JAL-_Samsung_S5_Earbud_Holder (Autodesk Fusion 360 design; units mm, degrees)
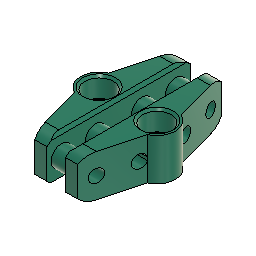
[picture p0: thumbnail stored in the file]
parameter "Structure_Thickness" = 2
parameter "Earbud_Main_Diameter" = 13.6
parameter "Earbud_Inner_Diameter" = 11
parameter "Wrap_Diameter" = 10
parameter "Plug_Diameter" = 6.2
parameter "Primary_Length_Short" = 34
sketch "Primary Layout"
  dimension "d44" = 17.6 (= "Earbud_Main_Diameter + ( Structure_Thickness * 2 )")
  dimension "d45" = 34 (= "Primary_Length_Short")
  dimension "d47" = 7
  dimension "d49" = 2 (= "Structure_Thickness")
  dimension "d50" = 5 (= "7 mm - Structure_Thickness")
extrude "Extrude1" new body sketch "Primary Layout" blind 20 bodies "Main Body"
sketch "Earbud holes" plane through (0, 0, 20) normal (0, 0, 1) x axis (-1, 0, 0)
  dimension "d55" = 13.6 (= "Earbud_Main_Diameter")
  dimension "d56" = 13.6 (= "Earbud_Main_Diameter")
  dimension "d57" = 11 (= "Earbud_Inner_Diameter")
  dimension "d58" = 11 (= "Earbud_Inner_Diameter")
extrude "Extrude2" sketch "Earbud holes" to an object
extrude "Extrude3" sketch "Earbud holes" blind -9.5
chamfer "Chamfer4" distance 1
sketch "Side Holes" plane through (0, 0, 0) normal (1, 0, 0) x axis (0, 1, 0)
  dimension "d80" = 10 (= "Wrap_Diameter")
  dimension "d81" = 6.2 (= "Plug_Diameter")
  dimension "d83" = 41.5873
  dimension "d84" = 16.2 (= "Wrap_Diameter + Plug_Diameter")
  dimension "d85" = 6.2 (= "Plug_Diameter")
  dimension "d86" = 7 (= "( Wrap_Diameter / 2 ) + 2 mm")
  dimension "d87" = 21.786
extrude "Extrude4" cut sketch "Side Holes" distance 4.45
chamfer "Chamfer1" distance 1.3
extrude "Extrude6" cut sketch "Side Holes" no distance stored
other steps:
create_component "CreateComponent2"
named bodies: "Main Body"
